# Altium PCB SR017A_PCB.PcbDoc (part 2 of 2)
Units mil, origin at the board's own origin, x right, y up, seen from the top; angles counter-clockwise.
Board outline 3000 x 2501 mil, 4 copper layers (Top Layer, GND Layer, Signal Layer, Bottom Layer), stack 59.4 mil thick; 53 components, 14 nets, 94 pads, 180 vias.
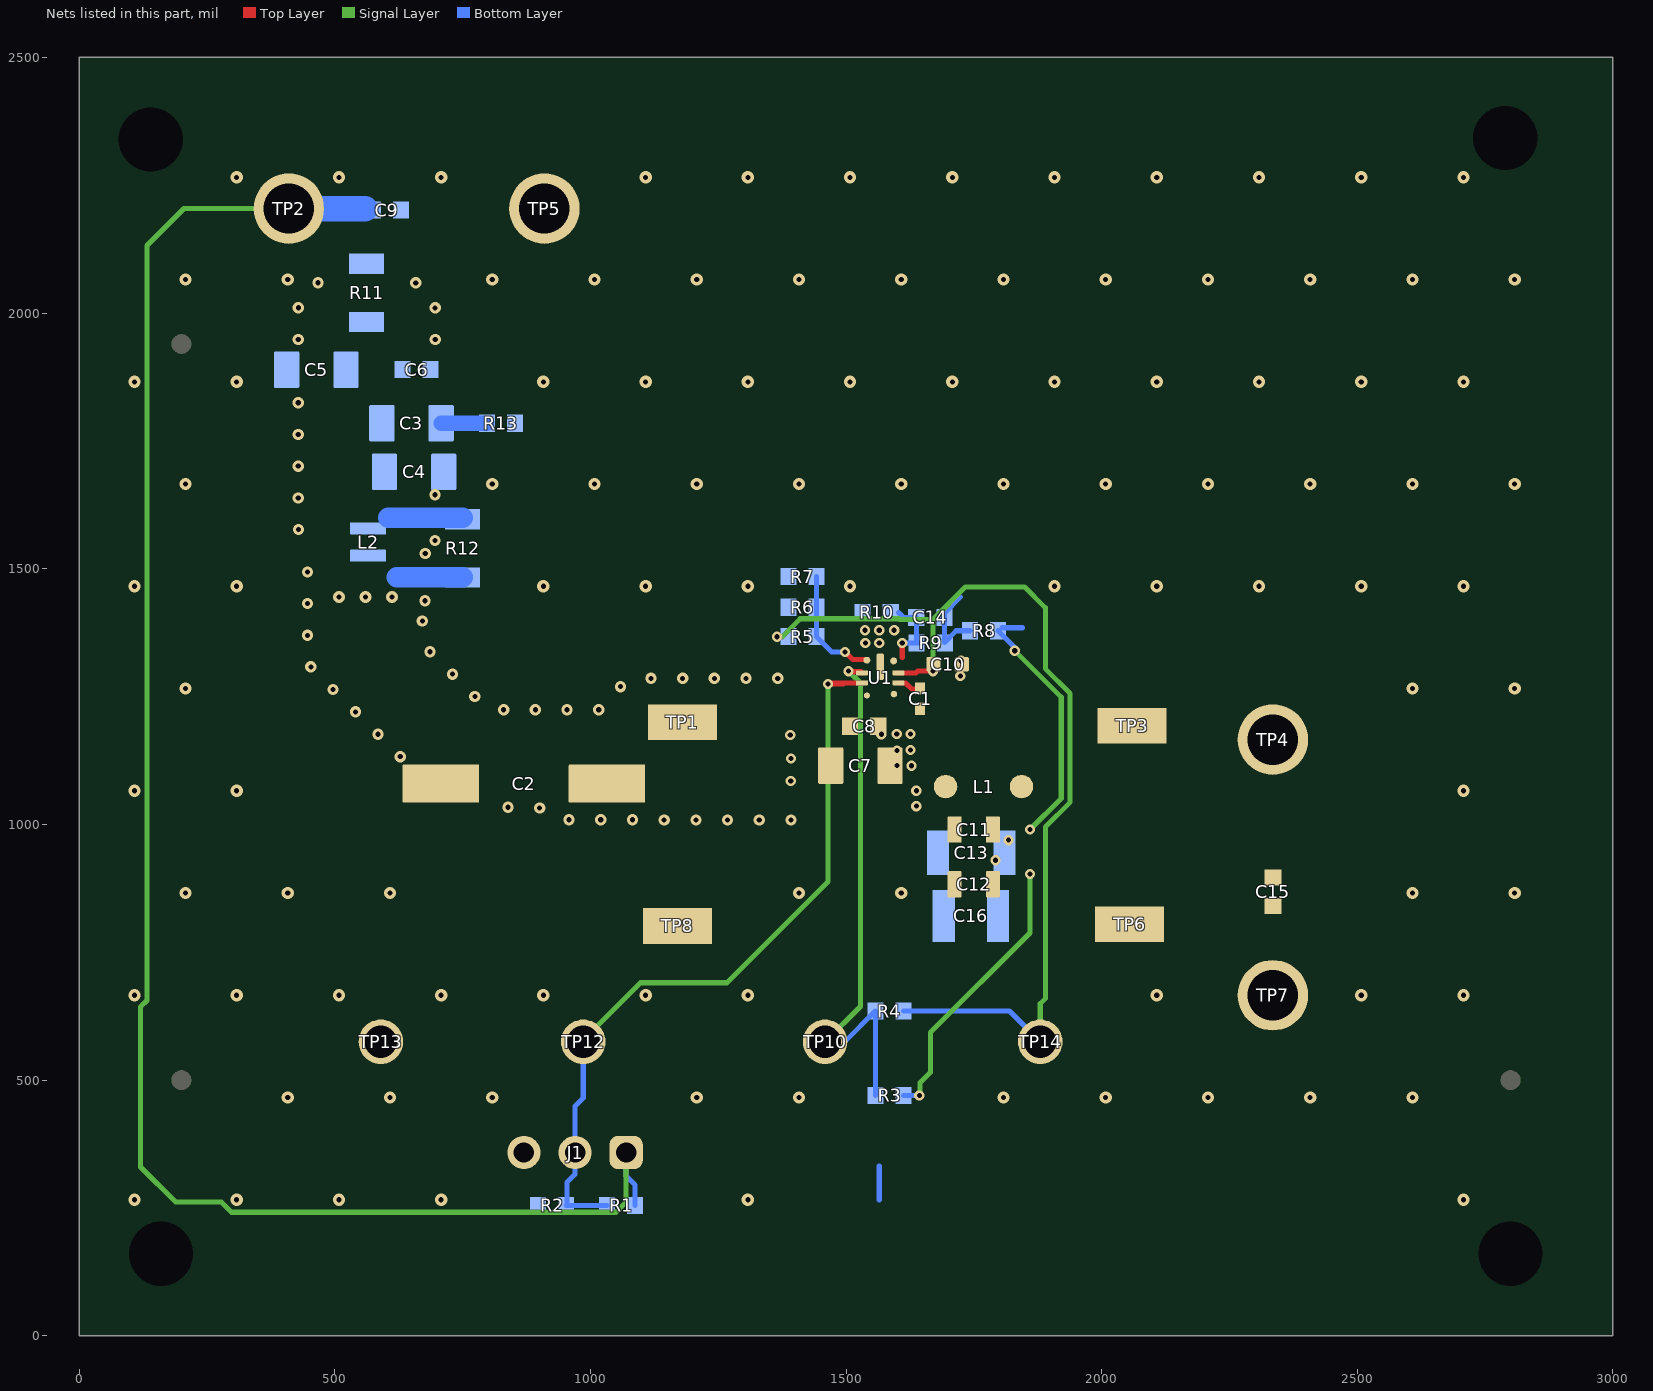
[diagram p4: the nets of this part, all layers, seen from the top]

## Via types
v1: diameter 24, hole 10, Top Layer to Bottom Layer, tented both sides, 102 vias
v2: diameter 22, hole 10, Top Layer to Bottom Layer, tented both sides, 47 vias
v3: diameter 20, hole 10, Top Layer to Bottom Layer, tented both sides, 23 vias
v4: diameter 20, hole 10, Top Layer to Bottom Layer, 8 vias

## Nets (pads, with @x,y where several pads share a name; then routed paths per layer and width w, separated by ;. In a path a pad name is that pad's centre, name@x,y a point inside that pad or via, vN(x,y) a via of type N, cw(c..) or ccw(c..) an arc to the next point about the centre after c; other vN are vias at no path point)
BOOT: C1.2 U1.6 | length 42.6
  Top Layer w10: U1.6@1602.39,1277.05 1616.47,1277.05 1628.52,1265 C1.2@1640,1265
EN: J1.2 R1.1 R2.2 TP12.1 U1.3 | length 1508.9
  Top Layer w10: v3@1464.67,1276.58 1464.84,1276.58 U1.3@1531.53,1277.05 U1.3@1532.13,1277.05 ; v3(1464.85,1275) 1495,1275
  Signal Layer w10: TP12.1@986,575 986,578.65 1097.85,690.5 1267.15,690.5 1464.85,888.2 v3(1464.85,1275)
  Bottom Layer w10: TP12.1@986,575 986,465 970,449 J1.2@970,358.35 970,315.74 954.26,300 954.26,256.7 R2.2@952.56,255 R1.1@1032.44,255
FB: C14.2 R9.1 R10.2 U1.8 | length 156.8
  Top Layer w10: 1610,1326.7 v3(1610,1355)
  Bottom Layer w10: R10.2@1602.56,1414.95 1612.51,1405 C14.2@1637.44,1405 1638.26,1404.18 R9.1@1638.26,1355.32 ; v3(1610,1355) R9.1@1649.52,1355
GND: C2.1 C4.1 C5.1 C6.2 C7.1 C8.2 C9.2 C10.1 C11.1 C12.1 C13.2 C15.1 C16.2 J1.3 R2.1 R6.1 R7.1 R10.1 R13.1 TP5.1 TP6.1 TP7.1 TP8.1 TP13.1 U1.9 | length 66
  Bottom Layer w10: 1565,266 1565,332
  other v1: 108,266 308,266 508,266 708,266 1308,266 2708,266 408,466 608,466 808,466 1208,466 1408,466 1808,466 2008,466 2208,466 2408,466 2608,466 108,666 308,666 508,666 708,666 908,666 1108,666 1308,666 2108,666 2508,666 2708,666 208,866 408,866 608,866 1408,866 1608,866 2608,866 2808,866 108,1066 308,1066 2708,1066 208,1266 2608,1266 2808,1266 108,1466 308,1466 908,1466 1108,1466 1308,1466 1508,1466 1908,1466 2108,1466 2308,1466 2508,1466 2708,1466 208,1666 808,1666 1008,1666 1208,1666 1408,1666 1608,1666 1808,1666 2008,1666 2208,1666 2408,1666 2608,1666 2808,1666 108,1866 308,1866 908,1866 1108,1866 1308,1866 1508,1866 1708,1866 1908,1866 2108,1866 2308,1866 2508,1866 2708,1866 208,2066 408,2066 808,2066 1008,2066 1208,2066 1408,2066 1608,2066 1808,2066 2008,2066 2208,2066 2408,2066 2608,2066 2808,2066 308,2266 508,2266 708,2266 1108,2266 1308,2266 1508,2266 1708,2266 1908,2266 2108,2266 2308,2266 2508,2266 2708,2266
  other v2: 958.33,1009.36 1020.33,1009.36 1082.33,1009.36 1144.32,1008.73 1206.32,1008.73 1268.32,1008.73 1330.32,1008.73 1392.32,1008.73 900.73,1032.3 838.74,1033.73 628.1,1132.68 584.26,1176.53 540.42,1220.37 830.26,1224.49 892.26,1224.49 954.26,1224.49 1016.26,1224.49 773.9,1250.32 496.57,1264.21 1058.66,1269.72 1118.48,1286 1180.48,1286 1242.48,1286 1304.48,1286 1366.48,1286 730.06,1294.16 453.15,1308.46 686.22,1338 446.73,1370.13 671.27,1398.17 446.73,1432.13 676.27,1437.8 446.73,1494.13 676.98,1530 696.01,1555.52 428.96,1576.97 428.56,1638.97 696.01,1645 428.56,1700.97 428.56,1762.97 428.56,1824.97 428.56,1948.97 696.44,1948.72 428.69,2010.97 696.35,2010.72 466.99,2059.73 658.31,2059.69
  other v3: 1637.56,1035.84 1637.56,1066 1628.02,1115 1626.22,1145.67 1599.21,1176.87 1626.04,1176.87 1537.79,1355 1565,1355 1537.29,1380 1565.14,1380 1594.22,1380
  other v4: 1600,1115.21 1599.64,1145 1569.14,1176.53 1723.63,1290.28 1725,1320.33
NetC3_1: C3.1 R13.2 | length 89.4
  Bottom Layer w30: C3.1@708.07,1785 R13.2@797.44,1785
NetC14_1: C14.1 R8.1 R9.2 | length 161.1
  Bottom Layer w10: 1723.63,1445 1692.56,1413.93 C14.1@1692.56,1405 1692.56,1356.14 1715.47,1379.05 R8.1@1742.44,1379.05
PGOOD: R3.2 R4.2 TP10.1 U1.2 | length 1081
  Top Layer w10: v3(1505,1300) 1506.05,1298.95 1529.31,1298.95 U1.2@1531.53,1296.73
  Signal Layer w10: TP10.1@1458,605 TP10.1@1459,604 ; TP10.1@1459,575 1528.2,644.2 1528.2,1276.8 v3(1505,1300)
  Bottom Layer w10: TP10.1@1459,575 1497.44,575 R4.2@1557.44,635 1557.76,634.68 R3.2@1557.76,470
RT: R5.2 R6.2 R7.2 U1.1 | length 235.8
  Top Layer w10: v3(1498.29,1337.67) 1513.46,1322.5 1540.92,1322.5 U1.1@1540.92,1321.41
  Bottom Layer w10: R7.2@1442.45,1485 1442.37,1484.92 R5.2@1442.37,1367.49 1472.19,1337.67 v3(1498.29,1337.67)
SW: C1.1 L1.1 U1.5
VCC: C10.2 R4.1 R5.1 TP14.1 U1.7 | length 1939.3
  Top Layer w10: U1.7@1602.39,1296.73 1636.73,1296.73 1640,1300 v4(1670,1300)
  Signal Layer w10: v3(1365,1367.26) 1375.32,1367.26 1410.56,1402.5 1603.54,1402.5 1605.04,1401 1670,1401 ; v4(1670,1300) 1670,1401 ; TP14.1@1880,575 1880,649.27 1890,659.27 1890,995.25 1938.49,1043.74 1938.49,1256.43 1890,1304.92 1890,1424 1849,1465 1734,1465 1670,1401
  Bottom Layer w10: R4.1@1612.56,635 1820,635 TP14.1@1880,575
Vin: C2.2 C7.2 C8.1 L2.2 R12.2 TP1.1 U1.4 | length 128.8
  Bottom Layer w10: R12.2@750,1483.11 R12.2@750,1483.47
  Bottom Layer w40: 621.53,1483.47 R12.2@750,1483.47
  other v1: 507.96,1445 560,1445 611.78,1445
  other v3: 1392,1085 1392.32,1129.31 1391.03,1175
VINX: C9.1 J1.1 R1.2 R11.1 TP2.1 | length 3466.7
  Signal Layer w10: TP2.1@410,2205 204.98,2205 132.5,2132.52 132.5,655.85 120,643.35 120,330 188.68,261.32 278.03,261.32 297.85,241.5 1050.18,241.5 1070,261.32 J1.1@1070,358.35
  Bottom Layer w10: J1.1@1070,358.35 1070,312.56 1087.56,295 R1.2@1087.56,255
  Bottom Layer w50: TP2.1@410,2205 C9.1@559,2205
VINY: C3.2 C4.2 C5.2 C6.1 L2.1 R11.2 R12.1 | length 149
  Bottom Layer w10: R12.1@750,1596.89 R12.1@750,1600.22
  Bottom Layer w40: 604.38,1600.22 R12.1@750,1600.22
VOUT: C11.2 C12.2 C13.1 C15.2 C16.1 L1.2 R3.1 R8.2 TP3.1 TP4.1 | length 1059
  Signal Layer w10: v3(1643.5,470.07) 1645,471.57 1645,495 1665,515 1665,593 1860,788 v3(1860,903.31) ; v3(1830.17,1340) 1920.99,1249.18 1920.99,1050.99 v3(1860,990)
  Bottom Layer w10: R3.1@1612.87,470 1612.94,470.07 v3(1643.5,470.07) ; R8.2@1797.56,1379.05 1830.17,1346.44 v3(1830.17,1340) ; R8.2@1805,1385 1845,1385
  other v4: 1792.24,930 1817.91,969.4
pads on no net: FID1.1 FID2.1 FID3.1 SH1.0

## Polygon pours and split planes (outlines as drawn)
GND on Top Layer "TOP_LAYER_GND_P096" (solid, remove dead copper, pour order 96): 47.57,2458.89 2947.57,2458.89 2947.57,58.89 47.57,58.89
no net on Top Layer "TOP_LAYER_NONET_P092" (solid, remove dead copper, pour order 92): 51.46,2455 2945,2455 2945,61.46 2941.46,65 55,65 55,2451.46
VOUT on Top Layer "TOP_LAYER_VOUT_P068" (solid, remove dead copper, pour order 68): 1771.61,1256.62 1860,1256.62 1860,983.37 1770.97,983.37 1771.61,984.01
Vin on Top Layer "Top Layer-Vin" (solid, remove dead copper, pour order 11): 1537.79,1151.22 1427.8,1040 1086,1040 1086,1254.73 1537.79,1254.73
VOUT on Top Layer "Top Layer-Vout" (solid, remove dead copper, pour order 10): 1771.23,873 2427.55,873 2427.55,1002.38 1771.23,1002.38
no net on Top Layer "TOP_LAYER_NONET_P090" (solid, remove dead copper, pour order 90): 1662.92,1217.44 1740,1217.44 1740,1080 1662.92,1080
GND on Signal Layer "SIGNAL_LAYER_GND_P088" (solid, remove dead copper, pour order 88): 2947.57,58.89 47.57,58.89 47.57,2458.89 2947.57,2458.89
Vin on Signal Layer "SIGNAL_LAYER_VIN_P084" (solid, remove dead copper, pour order 84): 895,1193.22 786.78,1193.22 640,1340 640,1475 478,1475 478,1327 740,1065 895,1065
Vin on Signal Layer "Signal Layer-Vin" (solid, remove dead copper, pour order 74): 1434.63,1065 783,1065 783,1193.22 1434.62,1193.22
GND on GND Layer "GND_LAYER_GND_P078" (solid, remove dead copper, pour order 78): 2947.57,58.89 47.57,58.89 47.57,2458.89 2947.57,2458.89
GND on Bottom Layer "BOTTOM_LAYER_GND_P098" (solid, remove dead copper, pour order 98): 47.57,2458.89 2947.57,2458.89 2947.57,58.89 47.57,58.89

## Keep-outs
Keep-Out Layer:
  text ".Layer_Name" at 577,-858.49 h60

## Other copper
Top Layer:
  rectangle net SW: 1635.62,1192.13 1661.18,1215.66
  rectangle net VOUT: 1965.36,935 2425.55,1263.76
  rectangle net FB: 1593.16,1315.95 1614.81,1332.94
  rectangle net SW: 1584.77,1226.17 1653.78,1246.17
  rectangle net SW: 1644.8,1217.44 1720,1246.17
  rectangle net SW: 1584.68,1227.81 1614.2,1257.83
  rectangle net Vin: 929.02,1045 1175,1120
  region net Vin: 1102.72,1061.65 1136.29,1095.22 1090.59,1140.92 1057.02,1107.35
  pour cut-out: 1627.95,1207.68 1627.48,1207.21 1627.48,1185.68 1660,1185.68 1661.64,1187.32 1661.64,1207.68
  text ".Layer_Name" at 577,-858.49 h60
Bottom Layer:
  rectangle net NetC14_1: 1711,1440 1775,1490
  rectangle net VOUT: 1835,1370.13 1900,1425.13
  rectangle net VINY: 480,1567.98 645,2010
  rectangle net Vin: 478,1420 645,1549.27
  rectangle net VINX: 537,2100.5 586,2189.38
  rectangle net VOUT: 1755,755.5 1881.17,1007.62
  text ".Layer_Name" at 577,-858.49 h60

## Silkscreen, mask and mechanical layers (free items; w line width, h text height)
Top Overlay:
  lines w10: 1440.02,950 1890.02,950 1890.42,1355 1440.42,1355 1440.02,950
  text "11mm x 10mm" at 1635,1374.02 h40
  text "ON" at 1038.35,245 h40
  text "OFF" at 830,241.5 h40
  text ".Layer_Name" at 577,-858.49 h60
Bottom Overlay:
  text "GND" at 1900,1555 h40
  text "A" at 1760,1505 h40
  text "VOS" at 1995,1380 h40
  text ".Layer_Name" at 577,-858.49 h60
Top Paste:
  text ".Layer_Name" at 577,-858.49 h60
Bottom Paste:
  text ".Layer_Name" at 577,-858.49 h60
Top Solder:
  rectangle: 1639.3,1195.19 1657.48,1207.68
  text ".Layer_Name" at 577,-858.49 h60
  text ".Layer_Name" at 577,-858.49 h60
Bottom Solder:
  rectangle: 1797.56,1466 1880,1530
  text ".Layer_Name" at 577,-858.49 h60
Drill Guide:
  text ".Layer_Name" at 577,-858.49 h60
M1 Board Outline:
  the board outline again, w10
M2 Board Dimensions:
  rectangle: 125,-400 500,-275
  rectangle: 0,-275 125,-150
  lines w7: 0,-275 1000,-275 ; 125,-400 125,-150 ; 250,-400 250,-150 ; 500,-400 500,-150 ; 750,-400 750,-150 ; 0,-400 0,-150 1000,-150 1000,-400 0,-400
  text ".Layer_Name" at 577,-858.49 h60
M3 3D STEP Top:
  text ".Layer_Name" at 577,-858.49 h60
M4 3D STEP Bottom:
  text ".Layer_Name" at 577,-858.49 h60
M5 Assembly Top:
  lines w10: -292,-930.17 6308,-930.17 ; -292,-726.83 6310,-726.83 ; -292,-523.5 -292,-1133.5 3713,-1133.5 6310,-1133.5 6310,-523.5 -291.5,-523.5 -291.5,-1133.5 1284,-1133.5 ; 2173,-1133.5 2173,-523.5 ; 3440,-726.83 3440,-523.5 ; 4280,-726.83 4280,-523.5 ; 4902,-1140 4902,-937.17
  text "COMPONENTS MARKED 'DNP' SHOULD NOT BE POPULATED." at 1153.5,-318.5 h60
  text "ASSEMBLY VARIANT:" at 1153,-434 h60
  text ".VariantName" at 2189,-434 h60
  text "PCB VIEWED FROM TOP SIDE" at -228.5,-655.67 h60
  text "BOARD #:" at 2248,-655.67 h60
  text ".PRJ_Number" at 2793.5,-655.67 h60
  text "REV:" at 3638,-655.67 h60
  text ".PCB_Rev" at 3929.5,-655.67 h60
  text "SVN REV:" at 4476,-655.67 h60
  text ".VersionControl_RevNumber" at 4982,-655.67 h60
  text "TID #:" at 2248,-859 h60
  text ".TID" at 2793.5,-859 h60
  text "PLOT NAME =" at -228.5,-1064.34 h60
  text ".plot_File_Name" at 577,-1064.34 h60
  text "GENERATED    :" at 2250,-1064.34 h60
  text ".Print_Date" at 3119.5,-1064.34 h60
  text ".Print_Time" at 3848.5,-1064.34 h60
  text "TEXAS INSTRUMENTS" at 5113,-1064.34 h60
M6 Assembly Bottom:
  lines w10: -292.5,-727.33 6309.5,-727.33 ; -290.5,-930.67 6309.5,-930.67 ; 1115.5,-1140.5 1115.5,-937.67 ; 1737.5,-727.33 1737.5,-524 ; 2577.5,-727.33 2577.5,-524 ; 3844.5,-1134 3844.5,-524 ; 4733.5,-1134 6309,-1134 6309,-524 -292.5,-524 -292.5,-1134 2304.5,-1134 6309.5,-1134 6309.5,-524
  text "COMPONENTS MARKED 'DNP' SHOULD NOT BE POPULATED." at 6102,-318 h60
  text ".VariantName" at 5058,-434 h60
  text "ASSEMBLY VARIANT:" at 6097,-434 h60
  text ".VersionControl_RevNumber" at 1035.5,-656.17 h60
  text "SVN REV:" at 1541.5,-656.17 h60
  text ".PCB_Rev" at 2088,-656.17 h60
  text "REV:" at 2379.5,-656.17 h60
  text ".PRJ_Number" at 3224,-656.17 h60
  text "BOARD #:" at 3769.5,-656.17 h60
  text "PCB VIEWED FROM BOTTOM SIDE" at 6246,-656.17 h60
  text ".TID" at 3224,-859.5 h60
  text "TID #:" at 3769.5,-859.5 h60
  text "TEXAS INSTRUMENTS" at 904.5,-1064.84 h60
  text ".Print_Time" at 2169,-1064.84 h60
  text ".Print_Date" at 2898,-1064.84 h60
  text "GENERATED    :" at 3767.5,-1064.84 h60
  text ".plot_File_Name" at 5440.5,-1064.84 h60
  text "PLOT NAME =" at 6246,-1064.84 h60
M9 Title Sheet:
  drawing of 57 lines, arcs and shapes, not listed
  text "1" at 739.84,8036.5 h70
  text "2" at 3235.5,8036.5 h70
  text "3" at 5724.84,8036.5 h70
  text "4" at 8231.51,8036.5 h70
  text "5" at 10730.5,8036.5 h70
  text "6" at 13235.5,8036.5 h70
  text "A" at -416.5,6893.5 h70
  text "A" at 14383.5,6893.5 h70
  text "B" at -416.5,4513.5 h70
  text "B" at 14383.5,4513.5 h70
  text "C" at -416.5,2138.5 h70
  text "C" at 14383.5,2138.5 h70
  text "PROJECT TITLE:" at 11343.5,277.5 h45
  text ".PRJ_Title" at 11393.5,144.17 h70
  text "DESIGNED FOR:" at 11343.5,-23.5 h45
  text ".PRJ_Customer" at 11393.5,-163.5 h70
  text "D" at -416.5,-231.5 h70
  text "D" at 14383.5,-231.5 h70
  text "FILE NAME:" at 11343.5,-323.5 h45
  text ".PCB_File_Name_No_Path" at 11393.5,-443.5 h70
  text "Texas Instruments (TI) and/or its licensors do not warrant the accuracy or completeness of this specification" at 6374,-605.34 h45
  text "ENGINEER:" at 11343.5,-613.5 h45
  text "LAYOUT BY:" at 12848.5,-613.5 h45
  text "or any information contained therein. TI and/or its licensors do not warrant that this design will meet" at 6329.01,-718 h45
  text ".PRJ_Engineer" at 11393.5,-768.49 h70
  text ".PCB_Layout" at 12899,-768.49 h70
  text "the specifications, will be suitable for your application or fit for any particular purpose, or will operate in" at 6329.01,-830.67 h45
  text ".Layer_Name" at 577,-858.49 h60
  text "ALTIUM DESIGNER VERSION:" at 12848.5,-923.5 h45
  text "an implementation. TI and/or its licensors do not warrant that the design is production worthy. You should" at 6329.01,-943.33 h45
  text "completely validate and test your design implementation to confirm the system functionality for your application." at 6374,-1056 h45
  text ".print_Scale" at 11393.5,-1056.83 h70
  text ".Application_BuildNumber" at 12899,-1056.83 h70
  text "1" at 739.84,-1263.5 h70
  text "2" at 3235.5,-1263.5 h70
  text "3" at 5724.84,-1263.5 h70
  text "4" at 8231.51,-1263.5 h70
  text "5" at 10730.5,-1263.5 h70
  text "6" at 13235.5,-1263.5 h70
M10 Fab Notes:
  drawing of 189 lines, arcs and shapes, not listed
  text "DESIGN INFORMATION" at 12382.02,6356.17 h60
  text "MIN. TRACK WIDTH:" at 11737.46,6224.05 h60
  text "8" at 12833.7,6224.05 h60
  text "MIL" at 12988.46,6224.05 h60
  text "MIN. CLEARANCE:" at 11737.46,6099.92 h60
  text "0.2" at 12773.7,6099.93 h60
  text "mm" at 12988.46,6099.92 h60
  text "MIN. VIA PAD SIZE:" at 11737.46,5975.8 h60
  text "24" at 12803.71,5975.8 h60
  text "MIL" at 12988.46,5975.8 h60
  text "0.05mm (2MIL)" at 12432.46,5845.9 h60
  text "MINIMUM ANNULAR RING" at 11408.23,5837.67 h60
  text "EXTERNAL" at 13140.46,5837.67 h60
  text "PER" at 11608.23,5727.55 h60
  text "IPC-D-275 CLASS 2 LEVEL C" at 11828.23,5727.54 h60
  text "MIL, HOLES" at 13316.46,5627.07 h60
  text "+/-" at 12924,5618.48 h60
  text "+/-" at 13778,5618.48 h60
  text "REGISTRATION TOLERANCES:" at 11408.23,5617.42 h60
  text "METAL" at 12608,5617.42 h60
  text "5" at 13184.2,5617.42 h60
  text "3" at 14017.2,5617.42 h60
  text "MIL" at 14133.46,5617.42 h60
  text "HOLE SIZE TOLERANCE (UNLESS OTHERWISE SPECIFIED):" at 11408.23,5519.1 h60
  text "+/-" at 13778,5516.23 h60
  text "3" at 14017.2,5515.17 h60
  text "MIL" at 14133.46,5515.17 h60
  text "MATERIAL:" at 11333.46,5377.52 h60
  text "FR-4 High Tg" at 12319.9,5249 h60
  text "X" at 11620,5245 h60
  text "FR-408" at 11754.46,5236.49 h60
  text "OTHER" at 13242.46,5236.49 h60
  text "60 MIL (1.6mm) +/-10%" at 12074.56,5093.46 h60
  text "X" at 11954.46,5091.01 h60
  text "THICKNESS:" at 11408.23,5085.24 h60
  text "OTHER" at 13359.46,5085.24 h60
  text "TOLERANCE:" at 11408.23,4946.92 h60
  text "X" at 12256.46,4946.92 h60
  text "ANSI IPC-6012 TYPE 3 CLASS 2" at 12434.48,4946.92 h60
  text "OTHER +/-" at 12434.46,4802.73 h60
  text "BOW & TWIST:" at 11408.23,4657.54 h60
  text "X" at 12256.46,4657.54 h60
  text "ANSI IPC-6012 TYPE 3 CLASS 2" at 12434.48,4657.54 h60
  text "OTHER +/-" at 12434.46,4510.85 h60
  text "DRILLING:" at 11333.46,4380.23 h60
  text "NC_DRILL FILES" at 13094.46,4275.04 h60
  text "REFERENCE:" at 11408.23,4271.1 h60
  text "X" at 12065.46,4271.01 h60
  text "AS SHOWN" at 12243.46,4271.1 h60
  text "X" at 12966.46,4271.1 h60
  text "OTHER" at 13392.46,4128.85 h60
  text "PTH COPPER THICKNESS:" at 11407.91,4125.32 h60
  text "X" at 12547.14,4125.32 h60
  text "20-30 um" at 12675.14,4125.32 h60
  text "BOARD FINISH:" at 11333.46,3977.73 h60
  text "SILKSCREEN:" at 11488.68,3867.6 h60
  text "X" at 12446.46,3867.6 h60
  text "TOP" at 12563.46,3867.6 h60
  text "X" at 12956.46,3867.6 h60
  text "BOTTOM" at 13074.46,3867.6 h60
  text "SILKSCREEN COLOR:" at 11488.68,3712.41 h60
  text "X" at 12445.46,3712.41 h60
  text "WHITE" at 12563.46,3712.41 h60
  text "OTHER" at 13074.46,3712.41 h60
  text "X" at 12576.46,3568.96 h60
  text "GREEN" at 12694.46,3568.96 h60
  text "OTHER" at 13312.46,3568.96 h60
  text "SOLDER RESIST COLOR:" at 11488.68,3562.1 h60
  text "X" at 12576.46,3414.71 h60
  text "MATTE" at 12694.46,3414.71 h60
  text "SEMI-GLOSS" at 13312,3414.07 h60
  text "IMMERSION GOLD (ENIG)" at 12394.46,3241.94 h60
  text "ENEPIG" at 13732,3234.72 h60
  text "SURFACE FINISH:" at 11333.46,3233.72 h60
  text "X" at 12216.46,3233.72 h60
  text "IMM. TIN/SILVER OR EQUIV" at 11663,3096.4 h60
  text "OTHER" at 13094.46,3092.47 h60
  text "X" at 12215,2940 h60
  text "ARRAY/PANEL:" at 11333.46,2937.09 h60
  text "CUT AND TRIM PER M1 BOARD OUTLINE" at 12394.46,2928.87 h60
  text "N.C. ROUTE" at 12394.46,2792.9 h60
  text "V. SCORE" at 13260.46,2792.9 h60
  text "CERTIFICATION:" at 11333.46,2663.77 h60
  text "MATERIALS AND WORKMANSHIP FOR ALL PCBS" at 12058.46,2663.77 h60
  text "TO MEET OR EXCEED THE REQUIREMENTS OF:" at 12058.46,2569.71 h60
  text "X" at 11695.97,2441.08 h60
  text "ANSI IPC-A-600F CLASS ->" at 11823.96,2441.08 h60
  text "X" at 13471.97,2441.08 h60
  text "2" at 13581.96,2441.08 h60
  text "1" at 13266.96,2439.58 h60
  text "3" at 13935.96,2439.58 h60
  text "X" at 12507.97,2293.39 h60
  text "RoHS" at 12635.96,2293.39 h60
  text "OTHER" at 13280.36,2293.39 h60
  text "PER ORDER" at 13677.42,2293.39 h60
  text "ALL BOARDS MUST MEET OR EXCEED UL94-V0 REQUIREMENTS." at 11361,2139.57 h60
  text "PCB MUST BEAR THE UL94V-0 UL REGISTERED MATERIAL ID NUMBER" at 11361,2023.5 h60
  text "ADDITIONAL REQUIREMENTS:" at 11333.46,1854.08 h60
  text "MICROSECTION:" at 11408.23,1746.95 h60
  text "YES" at 12313.96,1746.95 h60
  text "REQUIRED" at 13175.46,1602.62 h60
  text "BARE BOARD ELEC. TEST:" at 11408.23,1599.76 h60
  text "NONE" at 12713.96,1599.76 h60
  text "X" at 13057.46,1599.76 h60
  text "PER ORDER" at 13767.46,1599.76 h60
  text "XX MIL VIAS REQUIRE NON-CONDUCTIVE FILL AND PLANARIZE" at 11576.38,1394.82 h59
  text "XX MIL VIAS REQUIRE CONDUCTIVE FILL AND PLANARIZE" at 11584.38,1290.84 h60
  text "OUTER XX MIL VIAS REQUIRE 50 OHM SINGLE-ENDED IMPEDANCE" at 11583.39,1127.46 h58
  text "LAYER 2 & 3 (INNER LAYERS) XX MIL WIDE, XX MIL SPACE / TRACES REQUIRE 100 OHM DIFFERENTIAL IMPEDANCE" at 11575.39,891.74 h60
  text ".Layer_Name" at 577,-858.49 h60
M11 Gerber Information:
  lines w10: -292,-930.17 6308,-930.17 ; -292,-726.83 6310,-726.83 ; -292,-523.5 -292,-1133.5 3713,-1133.5 6310,-1133.5 6310,-523.5 -291.5,-523.5 -291.5,-1133.5 1284,-1133.5 ; 2173,-1133.5 2173,-523.5 ; 3440,-726.83 3440,-523.5 ; 4280,-726.83 4280,-523.5 ; 4902,-1140 4902,-937.17
  text "ALL ARTWORK VIEWED FROM TOP SIDE" at -228.5,-655.67 h60
  text "BOARD #:" at 2248,-655.67 h60
  text ".PRJ_Number" at 2793.5,-655.67 h60
  text "REV:" at 3638,-655.67 h60
  text ".PCB_Rev" at 3929.5,-655.67 h60
  text "SVN REV:" at 4476,-655.67 h60
  text ".VersionControl_RevNumber" at 4982,-655.67 h60
  text "LAYER NAME =" at -228.5,-858.49 h60
  text "TID #:" at 2248,-859 h60
  text ".TID" at 2793.5,-859 h60
  text "PLOT NAME =" at -228.5,-1064.34 h60
  text ".plot_File_Name" at 577,-1064.34 h60
  text "GENERATED    :" at 2250,-1064.34 h60
  text ".Print_Date" at 3119.5,-1064.34 h60
  text ".Print_Time" at 3848.5,-1064.34 h60
  text "TEXAS INSTRUMENTS" at 5113,-1064.34 h60
M12 Stackup:
  drawing of 295 lines, arcs and shapes, not listed
  text "Layer" at 6545.88,7654.68 h60
  text "Name" at 6955.79,7654.68 h60
  text "Material" at 7885.54,7654.68 h60
  text "Thickness" at 8745.3,7654.68 h60
  text "Constant" at 9395.14,7654.68 h60
  text "Board Layer Stack" at 9965,7654.68 h60
  text "1" at 6545.88,7534.68 h60
  text "Top Overlay" at 6955.79,7534.68 h60
  text "2" at 6545.88,7414.68 h60
  text "Top Solder" at 6955.79,7414.68 h60
  text "Solder Resist" at 7885.54,7414.68 h60
  text "0.40mil" at 8745.3,7414.68 h60
  text "3.5" at 9395.14,7414.68 h60
  text "3" at 6545.88,7294.68 h60
  text "Top Layer" at 6955.79,7294.68 h60
  text "Copper" at 7885.54,7294.68 h60
  text "2.80mil" at 8745.3,7294.68 h60
  text "4" at 6545.88,7174.68 h60
  text "Dielectric1" at 6955.79,7174.68 h60
  text "FR-4 High Tg" at 7885.54,7174.68 h60
  text "10.00mil" at 8745.3,7174.68 h60
  text "4.2" at 9395.14,7174.68 h60
  text "5" at 6545.88,7054.68 h60
  text "GND Layer" at 6955.79,7054.68 h60
  text "Copper" at 7885.54,7054.68 h60
  text "1.40mil" at 8745.3,7054.68 h60
  text "6" at 6545.88,6934.68 h60
  text "Dielectric 2" at 6955.79,6934.68 h60
  text "FR-4 High Tg" at 7885.54,6934.68 h60
  text "31.00mil" at 8745.3,6934.68 h60
  text "4.2" at 9395.14,6934.68 h60
  text "7" at 6545.88,6814.68 h60
  text "Signal Layer" at 6955.79,6814.68 h60
  text "Copper" at 7885.54,6814.68 h60
  text "1.40mil" at 8745.3,6814.68 h60
  text "8" at 6545.88,6694.68 h60
  text "Dielectric 3" at 6955.79,6694.68 h60
  text "FR-4 High Tg" at 7885.54,6694.68 h60
  text "10.00mil" at 8745.3,6694.68 h60
  text "4.2" at 9395.14,6694.68 h60
  text "9" at 6545.88,6574.68 h60
  text "Bottom Layer" at 6955.79,6574.68 h60
  text "Copper" at 7885.54,6574.68 h60
  text "2.80mil" at 8745.3,6574.68 h60
  text "10" at 6545.88,6454.68 h60
  text "Bottom Solder" at 6955.79,6454.68 h60
  text "Solder Resist" at 7885.54,6454.68 h60
  text "0.40mil" at 8745.3,6454.68 h60
  text "3.5" at 9395.14,6454.68 h60
  text "11" at 6545.88,6334.68 h60
  text "Bottom Overlay" at 6955.79,6334.68 h60
  text ".Layer_Name" at 577,-858.49 h60
M13 Component Bodies Top:
  text ".Layer_Name" at 577,-858.49 h60
M14 Component Bodies Bottom:
  text ".Layer_Name" at 577,-858.49 h60
M15 Courtyards Top:
  text ".Layer_Name" at 577,-858.49 h60
M16 Courtyards Bottom:
  text ".Layer_Name" at 577,-858.49 h60
Drill Drawing:
  circle w10: c5363.72,3393.96 r27.63
  lines w10: 5336.09,3007.19 5349.9,3007.19 5363.72,2993.38 5377.53,3007.19 5391.34,3007.19 5377.53,3021 5391.34,3034.82 5377.53,3034.82 5363.72,3048.63 5349.9,3034.82 5336.09,3034.82 5349.9,3021 5336.09,3007.19 ; 5336.09,3117.7 5363.72,3131.51 5391.34,3117.7 5377.53,3145.32 5391.34,3172.95 5363.72,3159.14 5336.09,3172.95 5349.9,3145.32 5336.09,3117.7 ; 5336.09,3255.83 5349.9,3255.83 5349.9,3242.02 5377.53,3242.02 5377.53,3255.83 5391.34,3255.83 5391.34,3283.46 5377.53,3283.46 5377.53,3297.27 5349.9,3297.27 5349.9,3283.46 5336.09,3283.46 5336.09,3255.83 ; 5336.09,3545.91 5391.34,3545.91 5363.72,3490.66 5336.09,3545.91
  lines w12: 5286,2956.08 8517.49,2956.08 ; 5286,3577.68 8517.49,3577.68 ; 5623.86,2831.76 5623.86,3702 ; 5955.86,2831.76 5955.86,3702 ; 6592.43,2831.76 6592.43,3702 ; 6851.57,2831.76 6851.57,3702 ; 7226.72,2831.76 7226.72,3702 ; 7951.05,2831.76 7951.05,3702 ; 5286,2831.76 8517.49,2831.76 8517.49,3702 5286,3702 5286,2831.76
  text "Symbol" at 5360.59,3614.98 h72
  text "Quantity" at 5661.16,3614.98 h72
  text "Finished Hole Size" at 5993.16,3614.98 h72
  text "Plated" at 6629.72,3614.98 h72
  text "Hole Type" at 6888.86,3614.98 h72
  text "Drill Layer Pair" at 7264.02,3614.98 h72
  text "Hole Tolerance" at 7988.35,3614.98 h72
  text "180" at 5661.16,3490.66 h60
  text "10.00mil (0.254mm)" at 5993.16,3490.66 h60
  text "PTH" at 6629.72,3490.66 h60
  text "Round" at 6888.86,3490.66 h60
  text "Top Layer - Bottom Layer" at 7264.02,3490.66 h60
  text "3" at 5661.16,3366.34 h60
  text "40.00mil (1.016mm)" at 5993.16,3366.34 h60
  text "PTH" at 6629.72,3366.34 h60
  text "Round" at 6888.86,3366.34 h60
  text "Top Layer - Bottom Layer" at 7264.02,3366.34 h60
  text "4" at 5661.16,3242.02 h60
  text "63.00mil (1.600mm)" at 5993.16,3242.02 h60
  text "PTH" at 6629.72,3242.02 h60
  text "Round" at 6888.86,3242.02 h60
  text "Top Layer - Bottom Layer" at 7264.02,3242.02 h60
  text "4" at 5661.16,3117.7 h60
  text "98.43mil (2.500mm)" at 5993.16,3117.7 h60
  text "PTH" at 6629.72,3117.7 h60
  text "Round" at 6888.86,3117.7 h60
  text "Top Layer - Bottom Layer" at 7264.02,3117.7 h60
  text "4" at 5661.16,2993.38 h60
  text "126.00mil (3.200mm)" at 5993.16,2993.38 h60
  text "PTH" at 6629.72,2993.38 h60
  text "Round" at 6888.86,2993.38 h60
  text "Top Layer - Bottom Layer" at 7264.02,2993.38 h60
  text "195 Total" at 5661.16,2869.06 h60
  text ".Layer_Name" at 577,-858.49 h60
M17 Embedded Cavity:
  text ".Layer_Name" at 577,-858.49 h60
M18 Embedded Assembly:
  text ".Layer_Name" at 577,-858.49 h60
M19 Embedded Keepout:
  text ".Layer_Name" at 577,-858.49 h60

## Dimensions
0,0 to 3000,0 on M2 Board Dimensions
0,0 to 3000,2500 on M2 Board Dimensions
0,-400 to 1000,-400 on M2 Board Dimensions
